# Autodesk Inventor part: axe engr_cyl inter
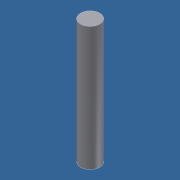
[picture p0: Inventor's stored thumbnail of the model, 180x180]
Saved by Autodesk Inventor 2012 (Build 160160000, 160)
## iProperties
Created: 2011-07
Part Number: axe engr_cyl inter
Document SubType Name: Modeling
Designer: Laur
Density: 7.85 g/cm^3
Material: Acier allié
Mass: 0.036649 g
Surface Area: 0.209004 cm^2
Volume: 0.00466866 cm^3
Author: Laur
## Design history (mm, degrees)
sketch "Esquisse1"
  geometry: C1 r 0.5 at (0, 0); 1 further point
  constraints: 1 centre point, 1 coincident
  dimensions: "d0" = 1 dimension on point (0, 0) C1.centre C1; "d0" = 1 diameter of C1
extrude "axe" new body sketch "Esquisse1" distance "d1" = 6.45; taper "d2" = 0 deg
node "Solide1"
node "Corps solides"
node "Corps surfaciques"
